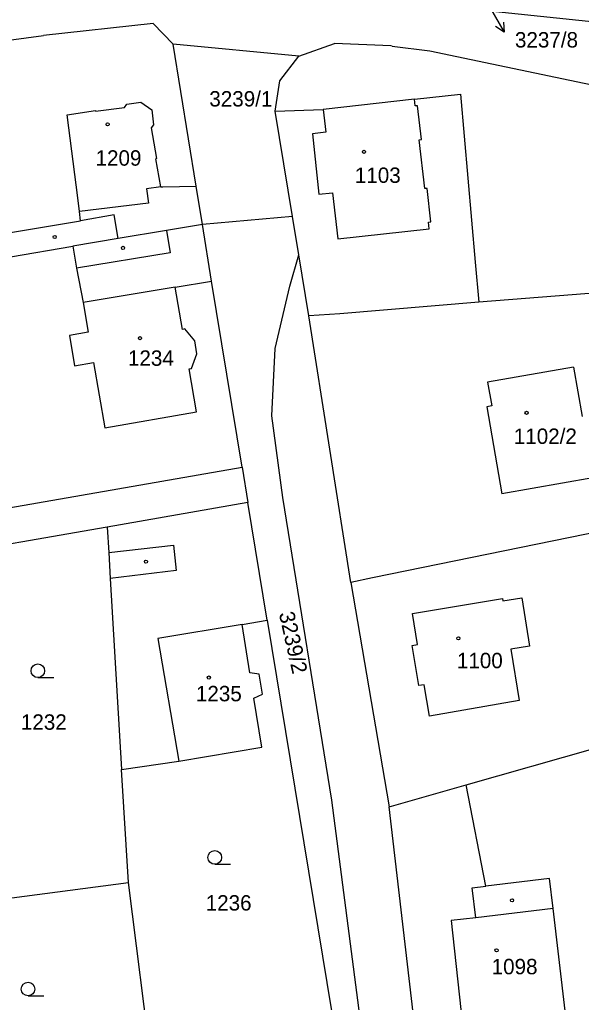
# Model space of a CAD drawing. Extents: x -736345 to -729997, y -1130177 to -1122501.
# Drawn here: x -734009.6 to -733947.7, y -1126710.1 to -1126601.7 of the extents above; entities that cross this region are included whole.
import ezdxf

# ---------------------------------------------------------------- set-up
doc = ezdxf.new("R2010")
doc.units = 0
for name, color, linetype in [('Vrstva 1', 7, 'Continuous'), ('Vrstva 16', 7, 'Continuous'), ('Vrstva 18', 7, 'Continuous'), ('Vrstva 19', 7, 'Continuous'), ('Vrstva 25', 7, 'Continuous'), ('Vrstva 4', 7, 'Continuous')]:
    doc.layers.add(name, color=color, linetype=linetype)

msp = doc.modelspace()

# ---------------------------------------------------------------- linework, layer by layer
at = {"layer": 'Vrstva 1'}
for points in [[(-733963.14, -1126600.17), (-733943.8, -1126602.19)], [(-733994.94, -1126602.12), (-734007, -1126603.45)], [(-733992.72, -1126604.41), (-733994.94, -1126602.12)], [(-734024.49, -1126605.8), (-734007, -1126603.45)], [(-733978.89, -1126605.73), (-733992.72, -1126604.41)], [(-733990.19, -1126620.07), (-733992.72, -1126604.41)], [(-733978.89, -1126605.73), (-733974.93, -1126604.33)], [(-733968.75, -1126604.61), (-733974.93, -1126604.33)], [(-733968.6, -1126604.62), (-733968.75, -1126604.61)], [(-733968.6, -1126604.62), (-733964.43, -1126605.15)], [(-733980.98, -1126608.46), (-733978.89, -1126605.73)], [(-733964.43, -1126605.15), (-733961.44, -1126605.78)], [(-733961.44, -1126605.78), (-733941.99, -1126609.87)], [(-733981.49, -1126611.81), (-733980.98, -1126608.46)], [(-733966.12, -1126610.49), (-733961.07, -1126609.93)], [(-733961.07, -1126609.93), (-733959.42, -1126628.47)], [(-733998.08, -1126611.4), (-733997.82, -1126611.05)], [(-733997.82, -1126611.05), (-733996.29, -1126610.81)], [(-733996.29, -1126610.81), (-733995.08, -1126611.67)], [(-733966.12, -1126610.49), (-733976.19, -1126611.61)], [(-734004.42, -1126612.2), (-734001.3, -1126611.74)], [(-734003.25, -1126621.35), (-734004.42, -1126612.2)], [(-734001.3, -1126611.74), (-734001.29, -1126611.82)], [(-734001.29, -1126611.82), (-733998.08, -1126611.4)], [(-733995.08, -1126611.67), (-733994.9, -1126613.3)], [(-733981.49, -1126611.81), (-733976.19, -1126611.61)], [(-733979.58, -1126623.42), (-733981.49, -1126611.81)], [(-733994.9, -1126613.3), (-733995.16, -1126613.64)], [(-733995.16, -1126613.64), (-733994.55, -1126617.04)], [(-733994.55, -1126617.04), (-733994.63, -1126617.06)], [(-733994.07, -1126620.17), (-733994.63, -1126617.06)], [(-733994.07, -1126620.17), (-733993.85, -1126620.15)], [(-733993.85, -1126620.15), (-733990.19, -1126620.07)], [(-733989.51, -1126624.3), (-733990.19, -1126620.07)], [(-734003.06, -1126622.87), (-734003.25, -1126621.35)], [(-734002.93, -1126623.89), (-734003.06, -1126622.87)], [(-734011.09, -1126625.26), (-734002.93, -1126623.89)], [(-733989.51, -1126624.3), (-733993.46, -1126624.97)], [(-733979.58, -1126623.42), (-733989.51, -1126624.3)], [(-733988.49, -1126630.56), (-733989.51, -1126624.3)], [(-733978.89, -1126627.65), (-733979.58, -1126623.42)], [(-733993.46, -1126624.97), (-733998.78, -1126625.87)], [(-733998.78, -1126625.87), (-734003.78, -1126626.71)], [(-734010.65, -1126627.87), (-734003.78, -1126626.71)], [(-734003.78, -1126626.71), (-734003.38, -1126629.14)], [(-733979.87, -1126631.13), (-733978.89, -1126627.65)], [(-733977.78, -1126634.39), (-733978.89, -1126627.65)], [(-733959.42, -1126628.47), (-733959.03, -1126632.89)], [(-734003.38, -1126629.14), (-734002.66, -1126632.93)], [(-733992.5, -1126631.23), (-733988.49, -1126630.56)], [(-733985.13, -1126651.07), (-733988.49, -1126630.56)], [(-733923.01, -1126630.03), (-733959.03, -1126632.89)], [(-733991.71, -1126635.88), (-733992.5, -1126631.23)], [(-733981.5, -1126637.99), (-733979.87, -1126631.13)], [(-734002.66, -1126632.93), (-734002.09, -1126636.2)], [(-733959.03, -1126632.89), (-733974.35, -1126634.17)], [(-733974.35, -1126634.17), (-733977.78, -1126634.39)], [(-733973.15, -1126663.81), (-733977.78, -1126634.39)], [(-734002.09, -1126636.2), (-734004.17, -1126636.57)], [(-733991.45, -1126635.83), (-733991.71, -1126635.88)], [(-733990.34, -1126637.14), (-733991.45, -1126635.83)], [(-734004.17, -1126636.57), (-734003.59, -1126639.9)], [(-733990.11, -1126638.59), (-733990.34, -1126637.14)], [(-733981.85, -1126645.43), (-733981.5, -1126637.99)], [(-733990.7, -1126640.2), (-733990.11, -1126638.59)], [(-734003.59, -1126639.9), (-734001.51, -1126639.53)], [(-734001.51, -1126639.53), (-734000.26, -1126646.75)], [(-733990.96, -1126640.24), (-733990.7, -1126640.2)], [(-733990.14, -1126644.98), (-733990.96, -1126640.24)], [(-733948.61, -1126640.06), (-733958.06, -1126641.72)], [(-733948.61, -1126640.06), (-733947.66, -1126645.5)], [(-733958.06, -1126641.72), (-733957.61, -1126644.33)], [(-733957.61, -1126644.33), (-733958.15, -1126644.42)], [(-733958.15, -1126644.42), (-733956.48, -1126654.01)], [(-734000.26, -1126646.75), (-733990.14, -1126644.98)], [(-733980.65, -1126654.44), (-733981.85, -1126645.43)], [(-734025.44, -1126658.1), (-733985.13, -1126651.07)], [(-733985.13, -1126651.07), (-733984.49, -1126655)], [(-733946.48, -1126652.27), (-733956.48, -1126654.01)], [(-733920.17, -1126652.96), (-733970.75, -1126663.31)], [(-733975.22, -1126687.82), (-733980.65, -1126654.44)], [(-733984.49, -1126655), (-734000, -1126657.69)], [(-733982.36, -1126667.98), (-733984.49, -1126655)], [(-734000, -1126657.69), (-734019.9, -1126661.15)], [(-734000, -1126657.69), (-733999.83, -1126660.49)], [(-733999.83, -1126660.49), (-733999.66, -1126663.38)], [(-733970.75, -1126663.31), (-733973.15, -1126663.81)], [(-733999.66, -1126663.38), (-733998.41, -1126684.43)], [(-733973.15, -1126663.81), (-733968.93, -1126688.58)], [(-733985.13, -1126668.44), (-733982.36, -1126667.98)], [(-733984.28, -1126673.77), (-733985.13, -1126668.44)], [(-733982.36, -1126667.98), (-733974.76, -1126714.2)], [(-733983.25, -1126673.91), (-733984.28, -1126673.77)], [(-733982.89, -1126676.13), (-733983.25, -1126673.91)], [(-733983.83, -1126676.58), (-733982.89, -1126676.13)], [(-733982.96, -1126681.99), (-733983.83, -1126676.58)], [(-733992.11, -1126683.51), (-733982.96, -1126681.99)], [(-733960.43, -1126686.15), (-733946.2, -1126682.08)], [(-733998.41, -1126684.43), (-733992.11, -1126683.51)], [(-733997.66, -1126696.9), (-733998.41, -1126684.43)], [(-733968.93, -1126688.58), (-733960.43, -1126686.15)], [(-733958.27, -1126697.33), (-733960.43, -1126686.15)], [(-733971.62, -1126715.56), (-733975.22, -1126687.82)], [(-733965.59, -1126717.28), (-733968.93, -1126688.58)], [(-734022, -1126700.11), (-733997.66, -1126696.9)], [(-733995.03, -1126717.59), (-733997.66, -1126696.9)], [(-733951.24, -1126696.49), (-733958.27, -1126697.33)], [(-733950.85, -1126699.8), (-733951.24, -1126696.49)], [(-733949.51, -1126711.07), (-733950.85, -1126699.8)]]:
    msp.add_lwpolyline(points, dxfattribs=at)
at = {"layer": 'Vrstva 25'}
for points in [[(-733957.76, -1126600.49), (-733956.256, -1126603.085)], [(-733956.325, -1126601.969), (-733956.256, -1126603.085), (-733957.19, -1126602.471)], [(-734007.64, -1126674.3), (-734005.89, -1126674.3)], [(-733988.14, -1126694.9), (-733986.39, -1126694.9)], [(-734008.72, -1126709.42), (-734006.97, -1126709.42)]]:
    msp.add_lwpolyline(points, dxfattribs=at)
for centre, radius in [((-733999.95, -1126613.26), 0.175), ((-733971.69, -1126616.29), 0.175), ((-734005.78, -1126625.68), 0.175), ((-733998.26, -1126626.89), 0.175), ((-733996.38, -1126636.85), 0.175), ((-733953.77, -1126645.09), 0.175), ((-733995.72, -1126661.51), 0.175), ((-733961.29, -1126669.97), 0.175), ((-734007.64, -1126673.55), 0.75), ((-733988.79, -1126674.3), 0.175), ((-733988.14, -1126694.15), 0.75), ((-733955.37, -1126698.88), 0.175), ((-733957.08, -1126704.39), 0.175), ((-734008.72, -1126708.67), 0.75)]:
    msp.add_circle(centre, radius, dxfattribs=at)
at = {"layer": 'Vrstva 4'}
for points in [[(-733966.04, -1126611.23), (-733966.12, -1126610.49)], [(-733965.78, -1126611.21), (-733966.04, -1126611.23)], [(-733965.36, -1126614.93), (-733965.78, -1126611.21)], [(-733976.19, -1126611.61), (-733975.91, -1126614.13)], [(-733975.91, -1126614.13), (-733977.37, -1126614.3)], [(-733977.37, -1126614.3), (-733976.66, -1126620.97)], [(-733965.61, -1126614.96), (-733965.36, -1126614.93)], [(-733965, -1126620.35), (-733965.61, -1126614.96)], [(-733994.07, -1126620.17), (-733995.65, -1126620.38)], [(-733995.65, -1126620.38), (-733995.45, -1126621.94)], [(-733976.66, -1126620.97), (-733975.16, -1126620.8)], [(-733975.16, -1126620.8), (-733974.59, -1126625.9)], [(-733964.74, -1126620.32), (-733965, -1126620.35)], [(-733964.32, -1126624.03), (-733964.74, -1126620.32)], [(-733995.45, -1126621.94), (-734003.06, -1126622.87)], [(-733999.22, -1126623.26), (-734002.93, -1126623.89)], [(-733998.78, -1126625.87), (-733999.22, -1126623.26)], [(-733964.58, -1126624.06), (-733964.32, -1126624.03)], [(-733964.5, -1126624.78), (-733964.58, -1126624.06)], [(-733993.46, -1126624.97), (-733993.05, -1126627.43)], [(-733974.59, -1126625.9), (-733964.5, -1126624.78)], [(-733993.05, -1126627.43), (-734003.38, -1126629.14)], [(-733992.5, -1126631.23), (-734002.66, -1126632.93)], [(-733999.83, -1126660.49), (-733992.7, -1126659.69)], [(-733992.7, -1126659.69), (-733992.39, -1126662.5)], [(-733992.39, -1126662.5), (-733999.66, -1126663.38)], [(-733956.37, -1126665.82), (-733954.3, -1126665.49)], [(-733954.3, -1126665.49), (-733953.43, -1126670.82)], [(-733966.35, -1126667.22), (-733956.41, -1126665.57)], [(-733956.41, -1126665.57), (-733956.37, -1126665.82)], [(-733965.78, -1126670.65), (-733966.35, -1126667.22)], [(-733985.13, -1126668.44), (-733994.42, -1126669.98)], [(-733994.42, -1126669.98), (-733992.11, -1126683.51)], [(-733966.37, -1126670.75), (-733965.78, -1126670.65)], [(-733965.64, -1126675.19), (-733966.37, -1126670.75)], [(-733953.43, -1126670.82), (-733955.51, -1126671.16)], [(-733955.51, -1126671.16), (-733954.59, -1126676.83)], [(-733965.04, -1126675.1), (-733965.64, -1126675.19)], [(-733964.47, -1126678.55), (-733965.04, -1126675.1)], [(-733954.59, -1126676.83), (-733964.47, -1126678.55)], [(-733959.76, -1126697.51), (-733958.27, -1126697.33)], [(-733959.37, -1126700.81), (-733959.76, -1126697.51)], [(-733950.85, -1126699.8), (-733959.37, -1126700.81)], [(-733959.37, -1126700.81), (-733962.07, -1126701.12)], [(-733962.07, -1126701.12), (-733960.84, -1126712.63)]]:
    msp.add_lwpolyline(points, dxfattribs=at)

# ---------------------------------------------------------------- texts
at = {"layer": 'Vrstva 16'}
msp.add_text('3237/8', height=1.7, dxfattribs=at).set_placement((-733955.05, -1126604.78))
at = {"layer": 'Vrstva 18'}
for s, p in [('3239/1', (-733988.74, -1126611.29)), ('1232', (-734009.51, -1126680.06)), ('1236', (-733989.14, -1126700.01))]:
    msp.add_text(s, height=1.7, dxfattribs=at).set_placement(p)
msp.add_text('3239/2', height=1.7, rotation=282.70225, dxfattribs=at).set_placement((-733981.081, -1126667.221))
at = {"layer": 'Vrstva 19'}
for s, p in [('1209', (-734001.28, -1126617.82)), ('1103', (-733972.7, -1126619.72)), ('1234', (-733997.71, -1126639.9)), ('1102/2', (-733955.18, -1126648.52)), ('1100', (-733961.45, -1126673.27)), ('1235', (-733990.22, -1126676.92)), ('1098', (-733957.62, -1126707.04))]:
    msp.add_text(s, height=1.7, dxfattribs=at).set_placement(p)

doc.saveas('drawing.dxf')
